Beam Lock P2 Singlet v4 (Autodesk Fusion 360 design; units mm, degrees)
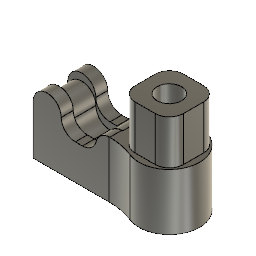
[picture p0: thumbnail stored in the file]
parameter "heatset_entry" = 5.2
parameter "heatset_depth" = 4
parameter "heatset_taperby" = 0.2
parameter "recip_thickness" = 3.2
parameter "recip_slotwidth" = 7
parameter "print_wall" = 0.435 (= "( 0.87 / 2 ) * 1 mm")
parameter "recip_distfrom" = 4.5
parameter "recip_tooth" = 1 comment "extra length to lock-in"
parameter "recip_slotdepth" = 10
sketch "Sketch1" plane through (0, 0, 0) normal (0, 0, 1) x axis (1, 0, 0)
  line L1 (-16, -1.6) -> (-12, -1.6)
  line L2 (-16, 1.6) -> (-16, -1.6)
  line L3 (-12, 1.6) -> (-16, 1.6)
  line L4 (-12, -1.6) -> (-12, 1.6)
  line L5 (0, 1.73) -> (0, 2.6)
  line L6 (0, -1.73) -> (0, -2.6)
  line L7 (0, 4.3) -> (0, 2.6)
  line L8 (0, -4.3) -> (0, -2.6)
  line L9 (-7, 1.6) -> (-12, 1.6)
  line L10 (-7, -1.6) -> (-12, -1.6)
  line L11 (-7, -1.6) -> (-7, 1.6)
  line L12 (-4, 1.6) -> (-7, 1.6)
  line L13 (-4, -1.6) -> (-4, 1.6)
  line L14 (-7, -1.6) -> (-4, -1.6)
  line L15 (-4, 3.3) -> (-4, 1.6)
  line L16 (-16, 3.3) -> (-4, 3.3)
  line L17 (-16, 1.6) -> (-16, 3.3)
  line L18 (-16, 0) -> (0, 0)
  line L19 (-12, 3.3) -> (-12, 1.6)
  line L20 (-7, 3.3) -> (-7, 1.6)
  line L21 (-2.7568, 3.3) -> (-4, 3.3)
  line L22 (3.43, -3.43) -> (-3.43, -3.43)
  line L23 (3.43, 3.43) -> (3.43, -3.43)
  line L24 (-3.43, 3.43) -> (3.43, 3.43)
  line L25 (-3.43, -3.43) -> (-3.43, 3.43)
  line L26 (3.43, 3.43) -> (-3.43, -3.43)
  line L27 (-3.43, 3.43) -> (3.43, -3.43)
  circle C1 centre (0, 0) radius 1.625
  circle C2 centre (0, 0) radius 3
  circle C3 centre (0, 0) radius 2.6
  circle C4 centre (0, 0) radius 1.73
  circle C5 centre (0, 0) radius 4.3
  point P1 (0, 0)
  point P2 (0, 0)
  point P5 (0, 0)
  point P10 (0, 2.6)
  point P11 (0, -2.6)
  point P12 (0, 1.73)
  point P13 (0, -1.73)
  point P14 (-12, 0)
  point P3 (0, 0)
  point P4 (0, 0)
  point P15 (0, 0)
  point P16 (0, 4.3)
  point P17 (0, -4.3)
  point P18 (-7, -1.6)
  point P21 (-7, -1.6)
  point P8 (-16, 1.6)
  point P24 (-16, 1.6)
  point P25 (0, 0)
  point P26 (-16, 0)
  point P27 (-12, 3.3)
  point P28 (-7, 3.3)
  point P30 (-2.7568, 3.3)
  point P35 (0, 0)
  point P36 (0, -3.43)
  point P37 (0, -1.73)
  point P7 (-16, -1.6)
  point P9 (-12, 1.6)
  point P20 (-4, -1.6)
  point P23 (-16, 3.3)
  coincident P1 P2
  concentric C1 C2
  concentric C2 C3
  coincident P1 P5
  horizontal L1
  vertical L2
  horizontal L3
  coincident C3 P10
  coincident C3 P11
  coincident C4 P12
  coincident C4 P13
  vertical L4
  midpoint L4 P14
  coincident P3 L5
  coincident P4 L6
  vertical L5
  vertical L6
  horizontal P1 P14
  coincident P1 P15
  coincident C5 P16
  vertical L7
  coincident C5 P17
  parallel L7 L8
  perpendicular L4 L9
  perpendicular L4 L10
  perpendicular L11 L12
  perpendicular L12 L13
  perpendicular L13 L14
  coincident P18 P21
  perpendicular L12 L15
  perpendicular L15 L16
  perpendicular L16 L17
  coincident P8 P24
  coincident P2 P25
  midpoint L2 P26
  coincident L16 P27
  perpendicular L16 L19
  coincident L16 P28
  perpendicular L16 L20
  vertical L20
  coincident C5 P30
  perpendicular L15 L21
  perpendicular L22 L23
  parallel L22 L24
  parallel L23 L25
  horizontal L22
  coincident L26 P35
  coincident L27 P35
  coincident P5 P35
  midpoint L22 P36
  coincident P13 P37
  equal L22 L25
  dimension "d1" diameter C1 = 3.25
  dimension "d2" diameter C2 = 6
  dimension "d3" diameter C3 = 5.2 (= "heatset_entry")
  dimension "d4" distance C3 C4 = 0.87 (= "print_wall * 2")
  dimension "d11" distance P7 P8 = 3.2 (= "recip_thickness")
  dimension "d29" distance P8 P9 = 4
  dimension "d69" distance P11 P17 = 1.7
  dimension "d70" distance L4 P18 = 5
  dimension "d71" distance P20 P21 = 3
  dimension "d72" distance P23 P24 = 1.7
  dimension "d95" distance P15 L13 = 4
  dimension "d99" distance P36 P37 = 1.7
  dimension "d104" distance P15 L22 = 3.43
extrude "Extrude7" new body sketch "Sketch1" profile of C3 C4 L2 L3 L4 L5 L6 C5 L7 L8 L9 L11 L12 L13 L14 L15 L16 L17 L18 L19 L20 L21 along normal blind 8 (= "heatset_depth + 4 mm")
extrude "Extrude9" cut sketch "Sketch1" profile of C3 C4 L5 L6 L18 along normal blind 4 (= "heatset_depth")
chamfer "Chamfer8" distance 0.2 (= "heatset_taperby") distance 4 (= "heatset_depth")
chamfer "Chamfer9" distance 0.4
extrude "Extrude8" sketch "Sketch1" profile of L4 C5 L9 L11 L16 L18 L19 L20 blind -4
extrude "Extrude10" sketch "Sketch1" profile of L9 L16 L19 L20 blind 1
extrude "Extrude11" sketch "Sketch1" profile of L3 L16 L17 L19 blind 1
fillet "Fillet12" radius 2
fillet "Fillet13" radius 2
fillet "Fillet14" radius 10
mirror "Mirror2"
combine "Combine2"
chamfer "Chamfer10" distance 0.87
extrude "Extrude12" sketch "Sketch1" profile of C3 C4 L5 L6 C5 L7 L8 L18 L21 L22 L23 L24 L25 blind 6.25
fillet "Fillet17" radius 2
